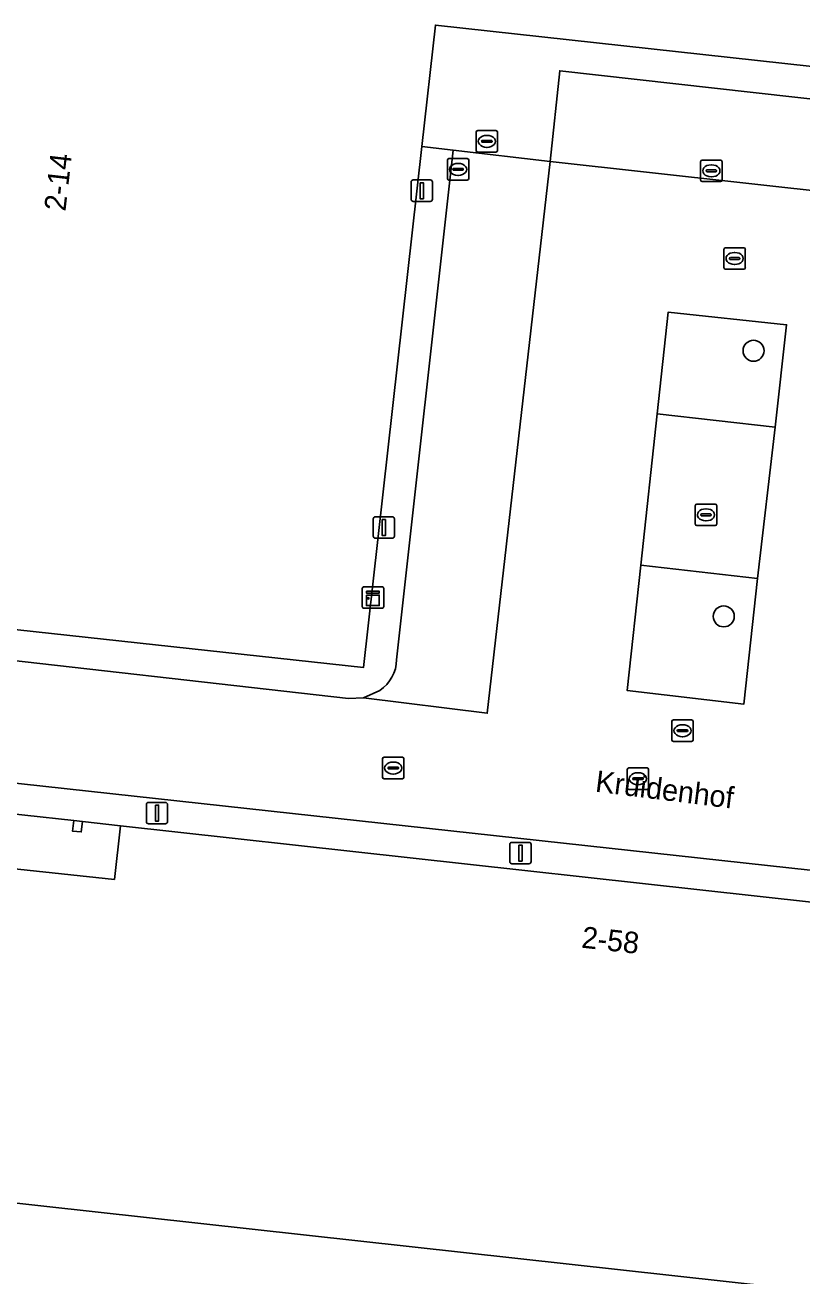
# Model space of a CAD drawing. Extents: x 162026 to 163502, y 387295 to 388169.
# Drawn here: x 162283.3 to 162319.6, y 387554 to 387612.3 of the extents above; entities that cross this region are included whole.
import ezdxf

# ---------------------------------------------------------------- set-up
doc = ezdxf.new("R2010")
doc.units = 0
for name, color, linetype in [('IMGEO_Boom', 7, 'Continuous'), ('IMGEO_Groenvoorziening', 7, 'Continuous'), ('IMGEO_Kast', 7, 'Continuous'), ('IMGEO_Kolk', 7, 'Continuous'), ('IMGEO_Lichtmast', 7, 'Continuous'), ('IMGEO_Openbare_ruimte_label', 7, 'Continuous'), ('IMGEO_Pand', 7, 'Continuous'), ('IMGEO_Pand_nummerreeks', 7, 'Continuous'), ('IMGEO_Pand_overbouw', 7, 'Continuous'), ('IMGEO_Parkeervlak_open', 7, 'Continuous'), ('IMGEO_Rijbaan_lokaal_open', 7, 'Continuous'), ('IMGEO_Rioolput', 7, 'Continuous'), ('IMGEO_Voetpad_open', 7, 'Continuous')]:
    doc.layers.add(name, color=color, linetype=linetype)

msp = doc.modelspace()

# ---------------------------------------------------------------- linework, layer by layer
at = {"layer": 'IMGEO_Boom'}
for centre in [(162317.306, 387597.126), (162315.916, 387584.74)]:
    msp.add_circle(centre, 0.489, dxfattribs=at)
at = {"layer": 'IMGEO_Groenvoorziening'}
for points in [[(162318.311, 387593.57), (162318.847, 387598.338), (162313.324, 387598.923), (162312.818, 387594.18)], [(162312.047, 387587.135), (162311.415, 387581.281), (162316.851, 387580.639), (162317.497, 387586.509)]]:
    msp.add_lwpolyline(points, close=True, dxfattribs=at)
at = {"layer": 'IMGEO_Kast'}
for p, q in [((162299.064, 387585.193), (162299.064, 387586.034)), ((162299.064, 387586.034), (162299.064, 387585.193)), ((162299.139, 387586.118), (162299.98, 387586.118)), ((162299.98, 387586.118), (162299.139, 387586.118)), ((162300.064, 387586.043), (162300.064, 387585.202)), ((162300.064, 387585.202), (162300.064, 387586.043)), ((162299.989, 387585.118), (162299.148, 387585.118)), ((162299.148, 387585.118), (162299.989, 387585.118))]:
    msp.add_line(p, q, dxfattribs=at)
for points in [[(162299.259, 387585.908), (162299.859, 387585.908), (162299.859, 387585.823), (162299.259, 387585.823), (162299.259, 387585.908)], [(162299.259, 387585.733), (162299.859, 387585.733), (162299.859, 387585.244), (162299.259, 387585.244), (162299.259, 387585.733)]]:
    msp.add_lwpolyline(points, dxfattribs=at)
msp.add_circle((162299.343, 387585.582), 0.0377, dxfattribs=at)
for centre, start, end in [((162299.142, 387586.04), 92.4484, 184.28452), ((162299.142, 387586.04), 92.4484, 184.28452), ((162299.986, 387586.04), 2.4484, 94.28452), ((162299.986, 387586.04), 2.4484, 94.28452), ((162299.142, 387585.196), 182.4484, 274.28452), ((162299.142, 387585.196), 182.4484, 274.28452), ((162299.986, 387585.196), 272.4484, 4.28452), ((162299.986, 387585.196), 272.4484, 4.28452)]:
    msp.add_arc(centre, 0.0779, start, end, dxfattribs=at)
at = {"layer": 'IMGEO_Kolk'}
for p, q in [((162315.922, 387601.002), (162315.922, 387601.854)), ((162315.997, 387601.928), (162316.849, 387601.928)), ((162316.41, 387601.708), (162316.435, 387601.708)), ((162316.923, 387601.854), (162316.923, 387601.002)), ((162316.181, 387601.422), (162316.181, 387601.434)), ((162316.619, 387601.385), (162316.221, 387601.385)), ((162316.224, 387601.471), (162316.622, 387601.471)), ((162316.433, 387601.148), (162316.408, 387601.148)), ((162316.665, 387601.434), (162316.665, 387601.422)), ((162316.849, 387600.928), (162315.997, 387600.928)), ((162314.588, 387589.05), (162314.588, 387589.902)), ((162314.663, 387589.976), (162315.515, 387589.976)), ((162315.589, 387589.902), (162315.589, 387589.05)), ((162314.847, 387589.47), (162314.847, 387589.482)), ((162315.285, 387589.433), (162314.887, 387589.433)), ((162314.89, 387589.519), (162315.288, 387589.519)), ((162315.076, 387589.756), (162315.101, 387589.756)), ((162315.331, 387589.482), (162315.331, 387589.47)), ((162315.515, 387588.976), (162314.663, 387588.976)), ((162315.099, 387589.196), (162315.074, 387589.196)), ((162313.494, 387578.983), (162313.494, 387579.835)), ((162313.569, 387579.909), (162314.421, 387579.909)), ((162313.753, 387579.403), (162313.753, 387579.415)), ((162313.796, 387579.452), (162314.194, 387579.452)), ((162313.982, 387579.689), (162314.007, 387579.689)), ((162314.237, 387579.415), (162314.237, 387579.403)), ((162314.495, 387579.835), (162314.495, 387578.983)), ((162314.421, 387578.909), (162313.569, 387578.909)), ((162314.191, 387579.366), (162313.793, 387579.366)), ((162314.005, 387579.129), (162313.98, 387579.129)), ((162300.008, 387577.242), (162300.008, 387578.094)), ((162300.083, 387578.168), (162300.935, 387578.168)), ((162300.267, 387577.662), (162300.267, 387577.674)), ((162300.31, 387577.711), (162300.708, 387577.711)), ((162300.496, 387577.948), (162300.521, 387577.948)), ((162300.751, 387577.674), (162300.751, 387577.662)), ((162301.009, 387578.094), (162301.009, 387577.242)), ((162300.935, 387577.168), (162300.083, 387577.168)), ((162300.705, 387577.625), (162300.307, 387577.625)), ((162300.519, 387577.388), (162300.494, 387577.388))]:
    msp.add_line(p, q, dxfattribs=at)
for points in [[(162315.922, 387601.002), (162315.922, 387601.854)], [(162315.997, 387601.928), (162316.849, 387601.928)], [(162316.923, 387601.854), (162316.923, 387601.002)], [(162316.849, 387600.928), (162315.997, 387600.928)], [(162314.588, 387589.05), (162314.588, 387589.902)], [(162314.663, 387589.976), (162315.515, 387589.976)], [(162315.589, 387589.902), (162315.589, 387589.05)], [(162315.515, 387588.976), (162314.663, 387588.976)], [(162313.494, 387578.983), (162313.494, 387579.835)], [(162313.569, 387579.909), (162314.421, 387579.909)], [(162314.495, 387579.835), (162314.495, 387578.983)], [(162314.421, 387578.909), (162313.569, 387578.909)], [(162300.008, 387577.242), (162300.008, 387578.094)], [(162300.083, 387578.168), (162300.935, 387578.168)], [(162301.009, 387578.094), (162301.009, 387577.242)], [(162300.935, 387577.168), (162300.083, 387577.168)]]:
    msp.add_lwpolyline(points, dxfattribs=at)
for centre, radius, start, end in [((162315.999, 387601.852), 0.0765, 91.55205, 178.44795), ((162315.999, 387601.852), 0.0765, 91.55205, 178.44795), ((162316.847, 387601.852), 0.0765, 1.55205, 88.44795), ((162316.847, 387601.852), 0.0765, 1.55205, 88.44795), ((162315.999, 387601.004), 0.0765, 181.55205, 268.44795), ((162315.999, 387601.004), 0.0765, 181.55205, 268.44795), ((162316.221, 387601.431), 0.0403, 85.87752, 175.75265), ((162316.218, 387601.421), 0.0366, 178.93798, 274.71019), ((162316.622, 387601.428), 0.043, 264.86636, 352.45326), ((162316.626, 387601.433), 0.0386, 1.73085, 96.63898), ((162316.847, 387601.004), 0.0765, 271.55205, 358.44795), ((162316.847, 387601.004), 0.0765, 271.55205, 358.44795), ((162314.665, 387589.9), 0.0765, 91.55205, 178.44795), ((162314.665, 387589.9), 0.0765, 91.55205, 178.44795), ((162315.513, 387589.9), 0.0765, 1.55205, 88.44795), ((162315.513, 387589.9), 0.0765, 1.55205, 88.44795), ((162314.887, 387589.479), 0.0403, 85.87752, 175.75265), ((162314.884, 387589.469), 0.0366, 178.93798, 274.71019), ((162315.288, 387589.476), 0.043, 264.86636, 352.45326), ((162315.292, 387589.481), 0.0386, 1.73085, 96.63898), ((162314.665, 387589.052), 0.0765, 181.55205, 268.44795), ((162314.665, 387589.052), 0.0765, 181.55205, 268.44795), ((162315.513, 387589.052), 0.0765, 271.55205, 358.44795), ((162315.513, 387589.052), 0.0765, 271.55205, 358.44795), ((162313.571, 387579.833), 0.0765, 91.55205, 178.44795), ((162313.571, 387579.833), 0.0765, 91.55205, 178.44795), ((162313.793, 387579.412), 0.0403, 85.87752, 175.75265), ((162313.79, 387579.402), 0.0366, 178.93798, 274.71019), ((162314.194, 387579.409), 0.043, 264.86636, 352.45326), ((162314.198, 387579.414), 0.0386, 1.73085, 96.63898), ((162314.419, 387579.833), 0.0765, 1.55205, 88.44795), ((162314.419, 387579.833), 0.0765, 1.55205, 88.44795), ((162313.571, 387578.985), 0.0765, 181.55205, 268.44795), ((162313.571, 387578.985), 0.0765, 181.55205, 268.44795), ((162314.419, 387578.985), 0.0765, 271.55205, 358.44795), ((162314.419, 387578.985), 0.0765, 271.55205, 358.44795), ((162300.085, 387578.092), 0.0765, 91.55205, 178.44795), ((162300.085, 387578.092), 0.0765, 91.55205, 178.44795), ((162300.307, 387577.671), 0.0403, 85.87752, 175.75265), ((162300.304, 387577.661), 0.0366, 178.93798, 274.71019), ((162300.708, 387577.668), 0.043, 264.86636, 352.45326), ((162300.712, 387577.673), 0.0386, 1.73085, 96.63898), ((162300.933, 387578.092), 0.0765, 1.55205, 88.44795), ((162300.933, 387578.092), 0.0765, 1.55205, 88.44795), ((162300.085, 387577.244), 0.0765, 181.55205, 268.44795), ((162300.085, 387577.244), 0.0765, 181.55205, 268.44795), ((162300.933, 387577.244), 0.0765, 271.55205, 358.44795), ((162300.933, 387577.244), 0.0765, 271.55205, 358.44795)]:
    msp.add_arc(centre, radius, start, end, dxfattribs=at)
for centre, major_axis, ratio, start_param, end_param in [((162316.409, 387601.428), (-0.387, 0.002), 0.722429, 4.712389, 7.853982), ((162316.434, 387601.428), (-0.39, 0.002), 0.717154, 1.570796, 4.712389), ((162315.075, 387589.476), (-0.387, 0.002), 0.722429, 4.712389, 7.853982), ((162315.1, 387589.476), (-0.39, 0.002), 0.717154, 1.570796, 4.712389), ((162313.981, 387579.409), (-0.387, 0.002), 0.722429, 4.712389, 7.853982), ((162314.006, 387579.409), (-0.39, 0.002), 0.717154, 1.570796, 4.712389), ((162300.495, 387577.668), (-0.387, 0.002), 0.722429, 4.712389, 7.853982), ((162300.52, 387577.668), (-0.39, 0.002), 0.717154, 1.570796, 4.712389)]:
    msp.add_ellipse(centre, major_axis=major_axis, ratio=ratio, start_param=start_param, end_param=end_param, dxfattribs=at)
at = {"layer": 'IMGEO_Lichtmast'}
for p, q in [((162301.443, 387605.088), (162302.233, 387605.088)), ((162302.233, 387605.088), (162301.443, 387605.088)), ((162301.343, 387604.188), (162301.343, 387604.988)), ((162301.343, 387604.988), (162301.343, 387604.188)), ((162302.333, 387604.988), (162302.333, 387604.188)), ((162302.333, 387604.188), (162302.333, 387604.988)), ((162302.233, 387604.088), (162301.443, 387604.088)), ((162301.443, 387604.088), (162302.233, 387604.088)), ((162299.676, 387589.382), (162300.466, 387589.382)), ((162300.466, 387589.382), (162299.676, 387589.382)), ((162299.576, 387588.482), (162299.576, 387589.282)), ((162299.576, 387589.282), (162299.576, 387588.482)), ((162300.566, 387589.282), (162300.566, 387588.482)), ((162300.566, 387588.482), (162300.566, 387589.282)), ((162300.466, 387588.382), (162299.676, 387588.382)), ((162299.676, 387588.382), (162300.466, 387588.382)), ((162288.999, 387575.167), (162288.999, 387575.967)), ((162288.999, 387575.967), (162288.999, 387575.167)), ((162289.099, 387576.067), (162289.889, 387576.067)), ((162289.889, 387576.067), (162289.099, 387576.067)), ((162289.989, 387575.967), (162289.989, 387575.167)), ((162289.989, 387575.167), (162289.989, 387575.967)), ((162289.889, 387575.067), (162289.099, 387575.067)), ((162289.099, 387575.067), (162289.889, 387575.067)), ((162306.042, 387574.203), (162306.832, 387574.203)), ((162306.832, 387574.203), (162306.042, 387574.203)), ((162305.942, 387573.303), (162305.942, 387574.103)), ((162305.942, 387574.103), (162305.942, 387573.303)), ((162306.932, 387574.103), (162306.932, 387573.303)), ((162306.932, 387573.303), (162306.932, 387574.103)), ((162306.832, 387573.203), (162306.042, 387573.203)), ((162306.042, 387573.203), (162306.832, 387573.203))]:
    msp.add_line(p, q, dxfattribs=at)
for points in [[(162301.763, 387604.963), (162301.913, 387604.963), (162301.913, 387604.213), (162301.763, 387604.213), (162301.763, 387604.963)], [(162299.996, 387589.257), (162300.146, 387589.257), (162300.146, 387588.507), (162299.996, 387588.507), (162299.996, 387589.257)], [(162289.419, 387575.942), (162289.569, 387575.942), (162289.569, 387575.192), (162289.419, 387575.192), (162289.419, 387575.942)], [(162306.362, 387574.078), (162306.512, 387574.078), (162306.512, 387573.328), (162306.362, 387573.328), (162306.362, 387574.078)]]:
    msp.add_lwpolyline(points, dxfattribs=at)
for centre, start, end in [((162301.443, 387604.988), 90, 180), ((162301.443, 387604.988), 90, 180), ((162302.233, 387604.988), 0, 90), ((162302.233, 387604.988), 360, 90), ((162301.443, 387604.188), 180, 270), ((162301.443, 387604.188), 180, 270), ((162302.233, 387604.188), 270, 0), ((162302.233, 387604.188), 270, 0), ((162299.676, 387589.282), 90, 180), ((162299.676, 387589.282), 90, 180), ((162300.466, 387589.282), 0, 90), ((162300.466, 387589.282), 360, 90), ((162299.676, 387588.482), 180, 270), ((162299.676, 387588.482), 180, 270), ((162300.466, 387588.482), 270, 0), ((162300.466, 387588.482), 270, 0), ((162289.099, 387575.967), 90, 180), ((162289.099, 387575.967), 90, 180), ((162289.889, 387575.967), 0, 90), ((162289.889, 387575.967), 360, 90), ((162289.099, 387575.167), 180, 270), ((162289.099, 387575.167), 180, 270), ((162289.889, 387575.167), 270, 0), ((162289.889, 387575.167), 270, 0), ((162306.042, 387574.103), 90, 180), ((162306.042, 387574.103), 90, 180), ((162306.832, 387574.103), 0, 90), ((162306.832, 387574.103), 360, 90), ((162306.042, 387573.303), 180, 270), ((162306.042, 387573.303), 180, 270), ((162306.832, 387573.303), 270, 0), ((162306.832, 387573.303), 270, 0)]:
    msp.add_arc(centre, 0.1, start, end, dxfattribs=at)
at = {"layer": 'IMGEO_Pand'}
for points in [[(162279.706, 387584.469), (162299.117, 387582.352), (162301.839, 387606.644), (162302.475, 387612.314), (162332.502, 387609.005), (162331.853, 387603.196), (162329.284, 387580.198), (162330.228, 387580.094), (162336.881, 387579.36), (162336.765, 387578.325), (162336.528, 387576.22), (162336.258, 387573.824), (162336.053, 387572.005), (162335.788, 387569.652), (162328.303, 387570.491), (162287.798, 387574.976), (162287.507, 387572.471), (162278.491, 387573.437)], [(162276.745, 387558.061), (162370.078, 387547.752)]]:
    msp.add_lwpolyline(points, dxfattribs=at)
msp.add_lwpolyline([(162285.611, 387575.218), (162285.555, 387574.731), (162285.962, 387574.686), (162286.019, 387575.173)], close=True, dxfattribs=at)
at = {"layer": 'IMGEO_Pand_overbouw'}
msp.add_lwpolyline([(162287.798, 387574.976), (162286.019, 387575.173), (162285.962, 387574.686), (162285.555, 387574.731), (162285.611, 387575.218), (162281.039, 387575.724), (162280.983, 387575.238), (162280.585, 387575.282), (162280.642, 387575.768), (162278.751, 387575.978), (162278.491, 387573.437), (162287.507, 387572.471)], close=True, dxfattribs=at)
at = {"layer": 'IMGEO_Parkeervlak_open'}
for points in [[(162326.063, 387603.928), (162326.449, 387608.135), (162308.27, 387610.183), (162307.832, 387605.954)], [(162317.497, 387586.509), (162318.311, 387593.57), (162312.818, 387594.18), (162312.047, 387587.135)]]:
    msp.add_lwpolyline(points, close=True, dxfattribs=at)
msp.add_lwpolyline([(162299.885, 387581.29), (162299.127, 387580.938), (162304.888, 387580.223), (162307.832, 387605.954), (162303.306, 387606.475), (162300.666, 387582.72)], dxfattribs=at)
msp.add_arc((162298.897, 387582.758), 1.77, 303.94748, 358.76986, dxfattribs=at)
at = {"layer": 'IMGEO_Rijbaan_lokaal_open'}
for points in [[(162307.832, 387605.954), (162304.888, 387580.223), (162299.127, 387580.938)], [(162326.063, 387603.928), (162307.832, 387605.954)], [(162298.426, 387580.903), (162279.501, 387583.06)], [(162299.127, 387580.938), (162298.426, 387580.903)], [(162278.897, 387577.398), (162328.456, 387571.969), (162328.303, 387570.491)]]:
    msp.add_lwpolyline(points, dxfattribs=at)
msp.add_lwpolyline([(162312.047, 387587.135), (162312.818, 387594.18), (162313.324, 387598.923), (162318.847, 387598.338), (162318.311, 387593.57), (162317.497, 387586.509), (162316.851, 387580.639), (162311.415, 387581.281)], close=True, dxfattribs=at)
at = {"layer": 'IMGEO_Rioolput'}
for p, q in [((162304.372, 387606.463), (162304.372, 387607.315)), ((162304.447, 387607.389), (162305.299, 387607.389)), ((162304.631, 387606.883), (162304.631, 387606.895)), ((162305.069, 387606.846), (162304.671, 387606.846)), ((162304.674, 387606.932), (162305.072, 387606.932)), ((162304.86, 387607.169), (162304.885, 387607.169)), ((162305.115, 387606.895), (162305.115, 387606.883)), ((162305.373, 387607.315), (162305.373, 387606.463)), ((162305.299, 387606.389), (162304.447, 387606.389)), ((162304.883, 387606.609), (162304.858, 387606.609)), ((162303.033, 387605.157), (162303.033, 387606.009)), ((162303.108, 387606.083), (162303.96, 387606.083)), ((162303.521, 387605.863), (162303.546, 387605.863)), ((162304.034, 387606.009), (162304.034, 387605.157)), ((162314.839, 387605.09), (162314.839, 387605.942)), ((162314.914, 387606.016), (162315.766, 387606.016)), ((162315.327, 387605.796), (162315.352, 387605.796)), ((162315.84, 387605.942), (162315.84, 387605.09)), ((162303.96, 387605.083), (162303.108, 387605.083)), ((162303.292, 387605.577), (162303.292, 387605.589)), ((162303.73, 387605.54), (162303.332, 387605.54)), ((162303.335, 387605.626), (162303.733, 387605.626)), ((162303.544, 387605.303), (162303.519, 387605.303)), ((162303.776, 387605.589), (162303.776, 387605.577)), ((162315.098, 387605.51), (162315.098, 387605.522)), ((162315.536, 387605.473), (162315.138, 387605.473)), ((162315.141, 387605.559), (162315.539, 387605.559)), ((162315.35, 387605.236), (162315.325, 387605.236)), ((162315.582, 387605.522), (162315.582, 387605.51)), ((162315.766, 387605.016), (162314.914, 387605.016)), ((162311.49, 387577.67), (162312.342, 387577.67)), ((162311.415, 387576.744), (162311.415, 387577.596)), ((162311.674, 387577.164), (162311.674, 387577.176)), ((162312.112, 387577.127), (162311.714, 387577.127)), ((162311.717, 387577.213), (162312.115, 387577.213)), ((162311.903, 387577.45), (162311.928, 387577.45)), ((162312.158, 387577.176), (162312.158, 387577.164)), ((162312.416, 387577.596), (162312.416, 387576.744)), ((162312.342, 387576.67), (162311.49, 387576.67)), ((162311.926, 387576.89), (162311.901, 387576.89))]:
    msp.add_line(p, q, dxfattribs=at)
for points in [[(162304.372, 387606.463), (162304.372, 387607.315)], [(162304.447, 387607.389), (162305.299, 387607.389)], [(162305.373, 387607.315), (162305.373, 387606.463)], [(162305.299, 387606.389), (162304.447, 387606.389)], [(162303.033, 387605.157), (162303.033, 387606.009)], [(162303.108, 387606.083), (162303.96, 387606.083)], [(162304.034, 387606.009), (162304.034, 387605.157)], [(162314.839, 387605.09), (162314.839, 387605.942)], [(162314.914, 387606.016), (162315.766, 387606.016)], [(162315.84, 387605.942), (162315.84, 387605.09)], [(162303.96, 387605.083), (162303.108, 387605.083)], [(162315.766, 387605.016), (162314.914, 387605.016)], [(162311.49, 387577.67), (162312.342, 387577.67)], [(162311.415, 387576.744), (162311.415, 387577.596)], [(162312.416, 387577.596), (162312.416, 387576.744)], [(162312.342, 387576.67), (162311.49, 387576.67)]]:
    msp.add_lwpolyline(points, dxfattribs=at)
for centre, radius, start, end in [((162304.449, 387607.313), 0.0765, 91.55205, 178.44795), ((162304.449, 387607.313), 0.0765, 91.55205, 178.44795), ((162304.671, 387606.892), 0.0403, 85.87752, 175.75265), ((162304.668, 387606.882), 0.0366, 178.93798, 274.71019), ((162305.072, 387606.889), 0.043, 264.86636, 352.45326), ((162305.076, 387606.894), 0.0386, 1.73085, 96.63898), ((162305.297, 387607.313), 0.0765, 1.55205, 88.44795), ((162305.297, 387607.313), 0.0765, 1.55205, 88.44795), ((162304.449, 387606.465), 0.0765, 181.55205, 268.44795), ((162304.449, 387606.465), 0.0765, 181.55205, 268.44795), ((162305.297, 387606.465), 0.0765, 271.55205, 358.44795), ((162305.297, 387606.465), 0.0765, 271.55205, 358.44795), ((162303.11, 387606.007), 0.0765, 91.55205, 178.44795), ((162303.11, 387606.007), 0.0765, 91.55205, 178.44795), ((162303.958, 387606.007), 0.0765, 1.55205, 88.44795), ((162303.958, 387606.007), 0.0765, 1.55205, 88.44795), ((162314.916, 387605.94), 0.0765, 91.55205, 178.44795), ((162314.916, 387605.94), 0.0765, 91.55205, 178.44795), ((162315.764, 387605.94), 0.0765, 1.55205, 88.44795), ((162315.764, 387605.94), 0.0765, 1.55205, 88.44795), ((162303.11, 387605.159), 0.0765, 181.55205, 268.44795), ((162303.11, 387605.159), 0.0765, 181.55205, 268.44795), ((162303.332, 387605.586), 0.0403, 85.87752, 175.75265), ((162303.329, 387605.576), 0.0366, 178.93798, 274.71019), ((162303.733, 387605.583), 0.043, 264.86636, 352.45326), ((162303.737, 387605.588), 0.0386, 1.73085, 96.63898), ((162303.958, 387605.159), 0.0765, 271.55205, 358.44795), ((162303.958, 387605.159), 0.0765, 271.55205, 358.44795), ((162314.916, 387605.092), 0.0765, 181.55205, 268.44795), ((162314.916, 387605.092), 0.0765, 181.55205, 268.44795), ((162315.138, 387605.519), 0.0403, 85.87752, 175.75265), ((162315.135, 387605.509), 0.0366, 178.93798, 274.71019), ((162315.539, 387605.516), 0.043, 264.86636, 352.45326), ((162315.543, 387605.521), 0.0386, 1.73085, 96.63898), ((162315.764, 387605.092), 0.0765, 271.55205, 358.44795), ((162315.764, 387605.092), 0.0765, 271.55205, 358.44795), ((162311.492, 387577.594), 0.0765, 91.55205, 178.44795), ((162311.492, 387577.594), 0.0765, 91.55205, 178.44795), ((162312.34, 387577.594), 0.0765, 1.55205, 88.44795), ((162312.34, 387577.594), 0.0765, 1.55205, 88.44795), ((162311.714, 387577.173), 0.0403, 85.87752, 175.75265), ((162311.711, 387577.163), 0.0366, 178.93798, 274.71019), ((162312.115, 387577.17), 0.043, 264.86636, 352.45326), ((162312.119, 387577.175), 0.0386, 1.73085, 96.63898), ((162311.492, 387576.746), 0.0765, 181.55205, 268.44795), ((162311.492, 387576.746), 0.0765, 181.55205, 268.44795), ((162312.34, 387576.746), 0.0765, 271.55205, 358.44795), ((162312.34, 387576.746), 0.0765, 271.55205, 358.44795)]:
    msp.add_arc(centre, radius, start, end, dxfattribs=at)
for centre, major_axis, ratio, start_param, end_param in [((162304.859, 387606.889), (-0.387, 0.002), 0.722429, 4.712389, 7.853982), ((162304.884, 387606.889), (-0.39, 0.002), 0.717154, 1.570796, 4.712389), ((162303.52, 387605.583), (-0.387, 0.002), 0.722429, 4.712389, 7.853982), ((162303.545, 387605.583), (-0.39, 0.002), 0.717154, 1.570796, 4.712389), ((162315.326, 387605.516), (-0.387, 0.002), 0.722429, 4.712389, 7.853982), ((162315.351, 387605.516), (-0.39, 0.002), 0.717154, 1.570796, 4.712389), ((162311.902, 387577.17), (-0.387, 0.002), 0.722429, 4.712389, 7.853982), ((162311.927, 387577.17), (-0.39, 0.002), 0.717154, 1.570796, 4.712389)]:
    msp.add_ellipse(centre, major_axis=major_axis, ratio=ratio, start_param=start_param, end_param=end_param, dxfattribs=at)
at = {"layer": 'IMGEO_Voetpad_open'}
for points in [[(162332.502, 387609.005), (162302.475, 387612.314), (162301.839, 387606.644), (162303.306, 387606.475), (162307.832, 387605.954), (162308.27, 387610.183), (162326.449, 387608.135), (162326.063, 387603.928), (162330.349, 387603.377), (162331.853, 387603.196)], [(162278.897, 387577.398), (162278.751, 387575.978), (162278.491, 387573.437), (162287.507, 387572.471), (162287.798, 387574.976), (162328.303, 387570.491), (162328.456, 387571.969)], [(162285.611, 387575.218), (162286.019, 387575.173), (162285.962, 387574.686), (162285.555, 387574.731)]]:
    msp.add_lwpolyline(points, close=True, dxfattribs=at)
for points in [[(162300.666, 387582.72), (162303.306, 387606.475), (162301.839, 387606.644), (162299.117, 387582.352), (162279.706, 387584.469)], [(162279.706, 387584.469), (162279.501, 387583.06), (162298.426, 387580.903), (162299.127, 387580.938), (162299.885, 387581.29)], [(162370.078, 387547.752), (162276.745, 387558.061), (162276.084, 387551.129)]]:
    msp.add_lwpolyline(points, dxfattribs=at)
msp.add_arc((162298.897, 387582.758), 1.77, 303.94748, 358.76986, dxfattribs=at)

# ---------------------------------------------------------------- texts
at = {"layer": 'IMGEO_Openbare_ruimte_label'}
msp.add_text('Kruidenhof', height=1, rotation=352.93186, dxfattribs=at).set_placement((162309.895, 387576.571))
at = {"layer": 'IMGEO_Pand_nummerreeks'}
for s, rotation, p in [('2-14', 83.53152, (162285.226, 387603.605)), ('2-58', 353.66882, (162309.254, 387569.295))]:
    msp.add_text(s, height=1, rotation=rotation, dxfattribs=at).set_placement(p)

doc.saveas('drawing.dxf')
